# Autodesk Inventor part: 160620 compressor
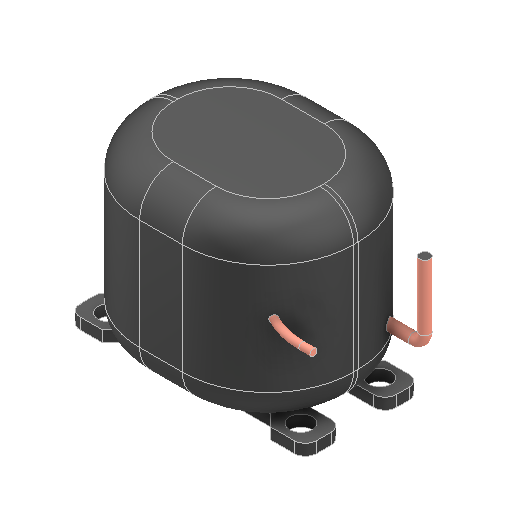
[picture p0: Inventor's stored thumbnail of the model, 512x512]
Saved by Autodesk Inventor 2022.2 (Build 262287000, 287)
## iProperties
Created: 2016-03
Part Number: 160620 compressor
Material: Generico
Document SubType Name: Modeling
Designer: 18907419
Density: 1 g/cm^3
Appearance: Default
Author: 18907419
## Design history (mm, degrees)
feature "Solido1"
feature "Solido2:1"
feature "Solido3:1"
node "Solido2"
node "Solido3"
node "Solido4"
